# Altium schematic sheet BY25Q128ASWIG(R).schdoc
size 127 x 101 mm
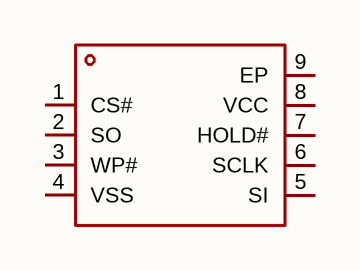
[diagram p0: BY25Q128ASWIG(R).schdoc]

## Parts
U?  by25q128aswig(r)  [WSON-8_L6.0-W5.0-P1.27-BL-EP]  (value not drawn)

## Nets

Not connected (* = marked no-connect by the designer): U? 1(CS#) 2(SO) 3(WP#) 4(VSS) 5(SI) 6(SCLK) 7(HOLD#) 8(VCC) 9(EP)

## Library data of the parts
U? = by25q128aswig(r): 接口类型:SPI;存储容量:128Mbit;时钟频率(fc):108MHz;; Manufacturer: BOYAMICRO(博雅); AddInBom: yes; ModelId: 72347fabc1e24788a361efd6527ab939; ModelName: WSON-8_L6.0-W5.0-H0.7-P1.27; ModelTransform: 237.007,196.85,0,90,0,0,0,0,0; Interface: SPI; Clock Frequency: 108MHz; Voltage - Supply: 2.7V~3.6V; Standby Supply Current: 5uA; Program / Erase Cycles: 100000次; Page Programming Time (Tpp): 700us; Data Retention - TDR (Year): 20年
